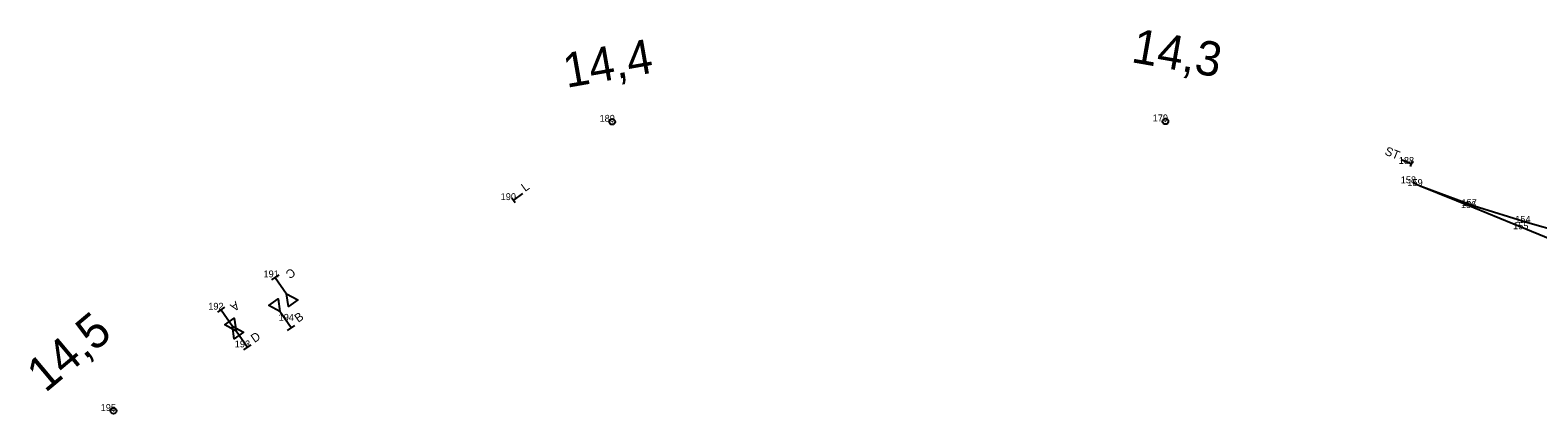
# Model space of a CAD drawing. Extents: x -554814 to -554052, y -1115925 to -1115523.
# Drawn here: x -554813.9 to -554550.8, y -1115590.1 to -1115523.2 of the extents above; entities that cross this region are included whole.
import ezdxf

# ---------------------------------------------------------------- set-up
doc = ezdxf.new("R2010")
doc.units = 0
for name, color, linetype in [('Vrstva 1', 7, 'Continuous'), ('Vrstva 4', 7, 'Continuous'), ('Vrstva 6', 7, 'Continuous'), ('Vrstva 60', 7, 'Continuous'), ('Vrstva 7', 7, 'Continuous')]:
    doc.layers.add(name, color=color, linetype=linetype)

msp = doc.modelspace()

# ---------------------------------------------------------------- linework, layer by layer
at = {"layer": 'Vrstva 1'}
for points in [[(-554546.75, -1115558.4), (-554552.5, -1115556.77), (-554561.86, -1115553.87), (-554571.31, -1115550.37), (-554572.47, -1115549.89)], [(-554547.34, -1115560.14), (-554552.85, -1115557.9), (-554561.96, -1115554.19), (-554571.31, -1115550.37), (-554572.47, -1115549.89)]]:
    msp.add_lwpolyline(points, dxfattribs=at)
at = {"layer": 'Vrstva 4'}
for p, q in [((-554770.5, -1115565.86), (-554771.78, -1115566.75)), ((-554779.96, -1115571.5), (-554781.23, -1115572.38)), ((-554768.96, -1115575.57), (-554767.68, -1115574.68)), ((-554776.6, -1115578.96), (-554775.32, -1115578.07))]:
    msp.add_line(p, q, dxfattribs=at)
for points in [[(-554771.14, -1115566.3), (-554769.15, -1115569.15), (-554767.19, -1115570.23), (-554768.82, -1115571.38), (-554769.15, -1115569.15)], [(-554780.59, -1115571.94), (-554778.6, -1115574.79), (-554776.65, -1115575.87), (-554778.28, -1115577.02), (-554778.6, -1115574.79)], [(-554768.32, -1115575.12), (-554770.31, -1115572.27), (-554772.27, -1115571.19), (-554770.63, -1115570.04), (-554770.31, -1115572.27)], [(-554775.96, -1115578.51), (-554777.95, -1115575.66), (-554779.91, -1115574.58), (-554778.27, -1115573.43), (-554777.95, -1115575.66)]]:
    msp.add_lwpolyline(points, dxfattribs=at)
at = {"layer": 'Vrstva 6'}
for p, q in [((-554574.64, -1115545.75), (-554572.81, -1115546.5)), ((-554573, -1115546.97), (-554572.62, -1115546.04)), ((-554729.86, -1115552.41), (-554729.27, -1115553.23)), ((-554727.96, -1115551.67), (-554729.56, -1115552.82))]:
    msp.add_line(p, q, dxfattribs=at)
at = {"layer": 'Vrstva 60'}
for p, q in [((-554712.3, -1115539.16), (-554712.3, -1115539.16)), ((-554615.76, -1115539.09), (-554615.76, -1115539.09)), ((-554572.81, -1115546.5), (-554572.81, -1115546.5)), ((-554572.47, -1115549.89), (-554572.47, -1115549.89)), ((-554571.31, -1115550.37), (-554571.31, -1115550.37)), ((-554729.56, -1115552.82), (-554729.56, -1115552.82)), ((-554561.96, -1115554.19), (-554561.96, -1115554.19)), ((-554561.86, -1115553.87), (-554561.86, -1115553.87)), ((-554552.85, -1115557.9), (-554552.85, -1115557.9)), ((-554552.5, -1115556.77), (-554552.5, -1115556.77)), ((-554771.14, -1115566.3), (-554771.14, -1115566.3)), ((-554780.59, -1115571.94), (-554780.59, -1115571.94)), ((-554768.32, -1115573.87), (-554768.32, -1115573.87)), ((-554775.96, -1115578.51), (-554775.96, -1115578.51)), ((-554799.36, -1115589.6), (-554799.36, -1115589.6))]:
    msp.add_line(p, q, dxfattribs=at)
at = {"layer": 'Vrstva 7'}
for p, q in [((-554712.25, -1115539.15), (-554712.34, -1115539.18)), ((-554615.71, -1115539.1), (-554615.81, -1115539.08)), ((-554799.32, -1115589.57), (-554799.4, -1115589.63))]:
    msp.add_line(p, q, dxfattribs=at)
for centre in [(-554712.3, -1115539.16), (-554615.76, -1115539.09), (-554799.36, -1115589.6)]:
    msp.add_circle(centre, 0.5, dxfattribs=at)

# ---------------------------------------------------------------- texts
at = {"layer": 'Vrstva 4'}
for s, rotation, p in [('C', 215, (-554768.28, -1115564.58)), ('A', 215, (-554778.04, -1115570.36)), ('B', 35, (-554767.11, -1115574.24)), ('D', 35, (-554774.73, -1115577.76))]:
    msp.add_text(s, height=1.5, rotation=rotation, dxfattribs=at).set_placement(p)
at = {"layer": 'Vrstva 6'}
for s, rotation, p in [('ST', 337.7308, (-554577.62, -1115544.83)), ('L', 35.6577, (-554727.52, -1115551.42))]:
    msp.add_text(s, height=1.5, rotation=rotation, dxfattribs=at).set_placement(p)
at = {"layer": 'Vrstva 60'}
for s, p in [('189', (-554714.53, -1115539.16)), ('179', (-554617.99, -1115539.09)), ('188', (-554575.04, -1115546.5)), ('158', (-554574.7, -1115549.89)), ('159', (-554573.54, -1115550.37)), ('190', (-554731.79, -1115552.82)), ('156', (-554564.19, -1115554.19)), ('157', (-554564.09, -1115553.87)), ('154', (-554554.72, -1115556.77)), ('155', (-554555.09, -1115557.9)), ('191', (-554773.18, -1115566.3)), ('192', (-554782.82, -1115571.94)), ('194', (-554770.54, -1115573.87)), ('193', (-554778.19, -1115578.51)), ('195', (-554801.6, -1115589.6))]:
    msp.add_text(s, height=1.2, dxfattribs=at).set_placement(p)
at = {"layer": 'Vrstva 7'}
for s, rotation, p in [('14,4', 10, (-554720.29, -1115533.26)), ('14,3', 350, (-554621.91, -1115528.73)), ('14,5', 40, (-554811.26, -1115586.54))]:
    msp.add_text(s, height=6, rotation=rotation, dxfattribs=at).set_placement(p)

doc.saveas('drawing.dxf')
